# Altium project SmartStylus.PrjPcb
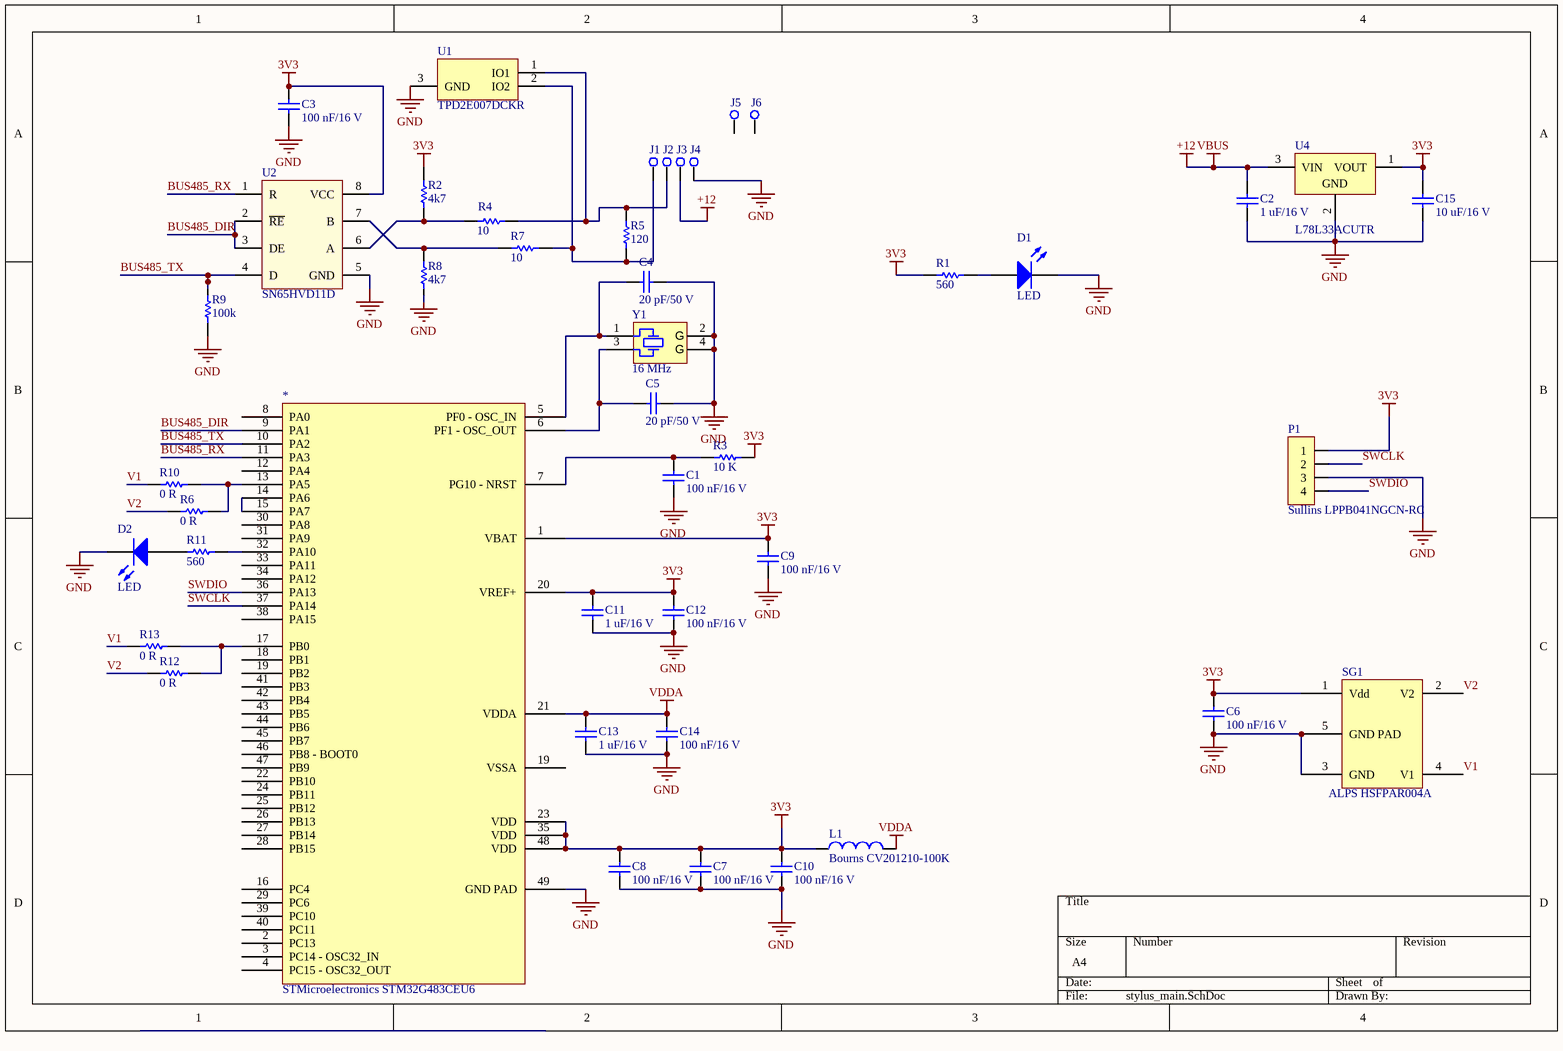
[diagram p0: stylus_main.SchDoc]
1 sheet, 44 parts. Net scope: global (net labels, ports and power ports of the same name join across sheets).

## Sheet stylus_main.SchDoc
size A4

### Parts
*  STMicroelectronics STM32G483CEU6  [PCB-xu7yg4drevi3r0790r64-1]
C1  100 nF/16 V  [CAPC1608X90X35LL15T15]
C2  1 uF/16 V  [CAPC1608X90X35LL15T15]
C3  100 nF/16 V  [CAPC1608X90X35LL15T15]
C4  20 pF/50 V  [CAPC1608X90X35LL15T15]
C5  20 pF/50 V  [CAPC1608X90X35LL15T15]
C6  100 nF/16 V  [CAPC1608X90X35LL15T15]
C7  100 nF/16 V  [CAPC1608X90X35LL15T15]
C8  100 nF/16 V  [CAPC1608X90X35LL15T15]
C9  100 nF/16 V  [CAPC1608X90X35LL15T15]
C10  100 nF/16 V  [CAPC1608X90X35LL15T15]
C11  1 uF/16 V  [CAPC1608X90X35LL15T15]
C12  100 nF/16 V  [CAPC1608X90X35LL15T15]
C13  1 uF/16 V  [CAPC1608X90X35LL15T15]
C14  100 nF/16 V  [CAPC1608X90X35LL15T15]
C15  10 uF/16 V  [CAPC1608X90X35LL15T15]
D1  LED  [PCB-nrpq7kty63qvmvgb1xe1-1]
D2  LED  [PCB-nrpq7kty63qvmvgb1xe1-1]
J1  (no value)  [PCB-8edmynyeb5ltl97ol5qu-1]
J2  (no value)  [PCB-8edmynyeb5ltl97ol5qu-1]
J3  (no value)  [PCB-8edmynyeb5ltl97ol5qu-1]
J4  (no value)  [PCB-8edmynyeb5ltl97ol5qu-1]
J5  (no value)  [PCB-8edmynyeb5ltl97ol5qu-1]
J6  (no value)  [PCB-8edmynyeb5ltl97ol5qu-1]
L1  Bourns CV201210-100K  [PCB-920965-1]
P1  Sullins LPPB041NGCN-RC  [PCB-ycrhwyuauqa1mfq2lwwg-1]
R1  560  [RESC1608X55X30LL15T15]
R2  4k7  [RESC1608X55X30LL15T15]
R3  10 K  [RESC1608X55X30LL15T15]
R4  10  [RESC1608X55X30LL15T15]
R5  120  [RESC1608X55X30LL15T15]
R6  0 R  [RESC1608X55X30LL15T15]
R7  10  [RESC1608X55X30LL15T15]
R8  4k7  [RESC1608X55X30LL15T15]
R9  100k  [RESC1608X55X30LL15T15]
R10  0 R  [RESC1608X55X30LL15T15]
R11  560  [RESC1608X55X30LL15T15]
R12  0 R  [RESC1608X55X30LL15T15]
R13  0 R  [RESC1608X55X30LL15T15]
SG1  ALPS HSFPAR004A  [PCB-o2yydmtgxd8iymg453x4-1]
U1  TPD2E007DCKR  [DCK3_N]
U2  SN65HVD11D  [PCB-8oqis65f0x56s0txpvqg-1]
U4  L78L33ACUTR  [SOT-89_L]
Y1  Frequency: 16 MHz  [PCB-gucbss5lviwmh6ifu49c-1]  (hidden comment: Abracon ABM3B-16.000MHZ-10-1-U-T)

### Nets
3V3: *.1(VBAT) *.20(VREF+) *.23(VDD) *.35(VDD) *.48(VDD) C3.1 C6.2 C7.1 C8.1 C9.1 C10.1 C11.1 C12.1 C15.1 L1.1 P1.1 R1.2 R2.2 R3.2 SG1.1(Vdd) U2.8(VCC) U4.1(VOUT)
+12: C2.2 J3.1 U4.3(VIN)  [also labelled VBUS]
GND: *.49(GND_PAD) C1.2 C2.1 C3.2 C4.2 C5.2 C6.1 C7.2 C8.2 C9.2 C10.2 C11.2 C12.2 C13.2 C14.2 C15.2 D1.2(K) D2.2(K) J4.1 P1.3 R8.1 R9.1 SG1.3(GND) SG1.5(GND_PAD) U1.3(GND) U2.5(GND) U4.2(GND) Y1.2(GND) Y1.4(GND)
VDDA: *.21(VDDA) C13.1 C14.1 L1.2
BUS485_DIR: *.9(PA1) U2.2(~{RE}) U2.3(DE)
BUS485_RX: *.11(PA3) U2.1(R)
BUS485_TX: *.10(PA2) R9.2 U2.4(D)
SWCLK: *.37(PA14) P1.2
SWDIO: *.36(PA13) P1.4
V1: R10.1 R13.1 SG1.4(V1)
V2: R6.1 R12.1 SG1.2(V2)
Net*_5: *.5(PF0_-_OSC_IN) C4.1 Y1.1
Net*_6: *.6(PF1_-_OSC_OUT) C5.1 Y1.3
Net*_7: *.7(PG10_-_NRST) C1.1 R3.1
Net*_13: *.13(PA5) R6.2 R10.2
Net*_14: *.14(PA6) *.15(PA7)
Net*_17: *.17(PB0) R12.2 R13.2
Net*_32: *.32(PA10) R11.2
NetD1_1: D1.1(A) R1.1
NetD2_1: D2.1(A) R11.1
NetJ1_1: J1.1 R5.2 R7.1 U1.2(IO2)
NetJ2_1: J2.1 R4.1 R5.1 U1.1(IO1)
NetR2_1: R2.1 R4.2 U2.6(A)
NetR7_2: R7.2 R8.2 U2.7(B)

Not connected (* = marked no-connect by the designer): * 2(PC13) 3(PC14_-_OSC32_IN) 4(PC15_-_OSC32_OUT) 8(PA0) 12(PA4) 16(PC4) 18(PB1) 19(PB2) 22(PB10) 24(PB11) 25(PB12) 26(PB13) 27(PB14) 28(PB15) 29(PC6) 30(PA8) 31(PA9) 33(PA11) 34(PA12) 38(PA15) 39(PC10) 40(PC11) 41(PB3) 42(PB4) 43(PB5) 44(PB6) 45(PB7) 46(PB8_-_BOOT0) 47(PB9); J5 1; J6 1

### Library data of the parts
* = CMP-43de8cfb153f9c19-2: Microcontroller 32-Bit ARM Cortex-M4 RISC 512K-Byte Flash 3.3V 48-Pin LQFP
C1 C6-C8 = CMP-15328962-11: 0603 0.1uF Capacitor; Insulation Resistance: 1e+11 Ω; Voltage Rating (DC): 16.0 V; Lead-Free Status: Lead Free; Dielectric Material: Ceramic Multilayer; Dielectric Characteristic: X7R; Capacitance Tolerance: ±10%; Capacitance: 1e-07 F; IFS PN: 100094
C2 = CMP-15328962-11: 0603 0.1uF Capacitor; Insulation Resistance: 1e+11 Ω; Voltage Rating (DC): 16.0 V; Lead-Free Status: Lead Free; Dielectric Material: Ceramic Multilayer; Dielectric Characteristic: X7R; Capacitance Tolerance: ±10%; Capacitance: 1e-07 F; IFS PN: 110435
C3 C9-C14 = CMP-15328962-11: 0603 0.1uF Capacitor; Insulation Resistance: 1e+11 Ω; Voltage Rating (DC): 16.0 V; Lead-Free Status: Lead Free; Dielectric Material: Ceramic Multilayer; Dielectric Characteristic: X7R; Capacitance Tolerance: ±10%; Capacitance: 1e-07 F; IF PN: 100094
C4 C5 = CMP-15328962-11: 0603 0.1uF Capacitor; Insulation Resistance: 1e+11 Ω; Voltage Rating (DC): 16.0 V; Lead-Free Status: Lead Free; Dielectric Material: Ceramic Multilayer; Dielectric Characteristic: X7R; Capacitance Tolerance: ±10%; Capacitance: 1e-07 F; IFS PN: 114775
C15 = CMP-15328962-11: 0603 0.1uF Capacitor; Insulation Resistance: 1e+11 Ω; Voltage Rating (DC): 16.0 V; Lead-Free Status: Lead Free; Dielectric Material: Ceramic Multilayer; Dielectric Characteristic: X7R; Capacitance Tolerance: ±10%; Capacitance: 1e-07 F; IFS PN: 101096
D1 D2 = CMP-1071566-5: 598-8110-107F, Dialight, SMD LED 0805 Package, Red Single color SOLD IN INCREMENTS OF 4000. (REEL)
J1-J6 = CMP-39b6f1ffc894e671-5: IC & Component Sockets Lo-pro Standard Stroke; .070 Sldr Mnt
L1 = CMP-920965-2: Ind Chip Shielded Multi-Layer 10uH 10% 2MHz 45Q-Factor Ferrite 15mA 0805 T/R; Inductance: 1e-05 H; Q-Factor: 45.0; IFS PN: 109017
P1 = CMP-bf0c76bda11c60cb-2: 4 Position Total Single Row 1.27 mm Pitch Right Angle Female Header; Lead-Free Status: Lead Free
R1 R6 R10-R13 = CMP-3652383-2: Thick Film Resistors - SMD 0603 FALSE 1% Tol; Manufacturer Part Number: ERJ-3RQF1R5V; Power Rating: 0.1 W; Resistance: 1.5 Ω; IFS PN: 100680
R2 R8 = CMP-3652383-2: Thick Film Resistors - SMD 0603 FALSE 1% Tol; Manufacturer Part Number: ERJ-3RQF1R5V; Power Rating: 0.1 W; Resistance: 1.5 Ω; IFS PN: 100673
R3 = CMP-3652383-2: Thick Film Resistors - SMD 0603 FALSE 1% Tol; Manufacturer Part Number: ERJ-3RQF1R5V; Power Rating: 0.1 W; Resistance: 1.5 Ω; IFS PN: 100042
R4 R7 = CMP-3652383-2: Thick Film Resistors - SMD 0603 FALSE 1% Tol; Manufacturer Part Number: ERJ-3RQF1R5V; Power Rating: 0.1 W; Resistance: 1.5 Ω; IFS PN: 102063
R5 = CMP-3652383-2: Thick Film Resistors - SMD 0603 FALSE 1% Tol; Manufacturer Part Number: ERJ-3RQF1R5V; Power Rating: 0.1 W; Resistance: 1.5 Ω
R9 = CMP-3652383-2: Thick Film Resistors - SMD 0603 FALSE 1% Tol; Manufacturer Part Number: ERJ-3RQF1R5V; Power Rating: 0.1 W; Resistance: 1.5 Ω; IFS PN: 102703
SG1 = CMP-101bdf21a62ccfdc-5: Force Sensor Gauge 0N to 8N 1.5V to 3.6V 4-Pin Surface Mount T/R
U1 = CMP-19354237-2: ESD Protection Array for AC Signal Data Interface, 2 Channels, -40 to +85 degC, 3-pin SC70 (DCK), Green (RoHS & no Sb/Br); Capacitance: 1.5e-11 F; Lead-Free Status: Lead Free; Number of Channels: 2
U2 = CMP-b61e7f1e772b69d9-1: RS-485 Interface ICs 3.3V Differential Transceivers; Drivers Per Package: 1
U4 = CMP-1171128-2: Positive Voltage Regulator, 3.3V, 4-Pin SOT-89, Tape and Reel; Dropout Voltage: 1.7 V; Lead-Free Status: Lead Free; Number of Outputs: 1; Output Current: 0.1 A
Y1 = CMP-9d295427774242ee-3: 16MHz ±10ppm Crystal 10pF 50 Ohm -10°C ~ 60°C Surface Mount 4-SMD, No Lead (DFN, LCC); Manufacturer Part Number, Other: 300-8206-1; Vendor Part Number: 300-8206-1-ND; Manufacturer: Abracon LLC; Operating Mode: Fundamental; Vendor: Digikey; ESR (Equivalent Series Resistance): 50 Ohm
